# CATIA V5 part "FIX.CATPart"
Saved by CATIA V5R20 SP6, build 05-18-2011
Part number: FIX
Bounding box of the stored display mesh (mm): x -700 to 700, y 0 to 20, z 0 to 1074.99
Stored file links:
  E:\#01 CATIA Lecture Materials\#06 DMU\#01 DMU KIN Page01 EX01\#01 CATPart\FIX.CATPart
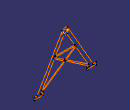
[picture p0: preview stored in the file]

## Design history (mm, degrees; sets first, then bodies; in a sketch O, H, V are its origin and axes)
AxisSystem1: origin (0, 0, 1000), X (1, 0, 0), Y (0, 1, 0), Z (0, 0, 1)
Set1
  DatumCurve1 "Curve.1 ( *CRV1 - wsp *MASTER -  )"
  DatumCurve2 "Curve.2 ( *CRV2 - wsp *MASTER -  )"
  Line1 "Line.1 ( *LN1 - wsp *MASTER -  )": stored without definition
  Line2 "Line.2 ( *LN2 - wsp *MASTER -  )": stored without definition
  Line3 "Line.3 ( *LN3 - wsp *MASTER -  )": stored without definition
  Line4 "Line.4 ( *LN4 - wsp *MASTER -  )": stored without definition
  Line5 "Line.5 ( *LN5 - wsp *MASTER -  )": stored without definition
  Line6 "Line.6 ( *LN6 - wsp *MASTER -  )": stored without definition
  Line7 "Line.7 ( *LN7 - wsp *MASTER -  )": stored without definition
  Line8 "Line.8 ( *LN8 - wsp *MASTER -  )": stored without definition
  Line9 "Line.9 ( *LN9 - wsp *MASTER -  )": stored without definition
  Line10 "Line.10 ( *LN10 - wsp *MASTER -  )": stored without definition
  Line11 "Line.11 ( *LN11 - wsp *MASTER -  )": stored without definition
  Line12 "Line.12 ( *LN12 - wsp *MASTER -  )": stored without definition
  Line13 "Line.13 ( *LN13 - wsp *MASTER -  )": stored without definition
  Line14 "Line.14 ( *LN14 - wsp *MASTER -  )": stored without definition
  Line15 "Line.15 ( *LN15 - wsp *MASTER -  )": stored without definition
  Line16 "Line.16 ( *LN16 - wsp *MASTER -  )": stored without definition
  Line17 "Line.17 ( *LN17 - wsp *MASTER -  )": stored without definition
  Line18 "Line.18 ( *LN18 - wsp *MASTER -  )": stored without definition
  Line19 "Line.19 ( *LN19 - wsp *MASTER -  )": stored without definition
  Line20 "Line.20 ( *LN20 - wsp *MASTER -  )": stored without definition
  Line21 "Line.21 ( *LN21 - wsp *MASTER -  )": stored without definition
  Line22 "Line.22 ( *LN22 - wsp *MASTER -  )": stored without definition
  Point1 "Point.7 ( PTM - wsp *MASTER -  )": stored without definition
Set2
  Point2 "Point.7 ( PTM - wsp *MASTER -  )": stored without definition
  Line23: type PtDir, RefPoint Point2, Direction (0, 1, 0), Start 0, End 20
Body1 (main body)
